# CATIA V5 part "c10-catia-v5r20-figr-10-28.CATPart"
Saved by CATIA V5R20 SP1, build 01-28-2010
Part number: Part1
Bounding box of the stored display mesh (mm): x -60 to 70, y 0 to 100.393, z 0 to 0
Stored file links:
  D:\v5_r20\psrt_files_downloaded\c10\c10-catia-v5r20-figr-10-28.CATPart
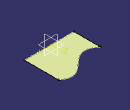
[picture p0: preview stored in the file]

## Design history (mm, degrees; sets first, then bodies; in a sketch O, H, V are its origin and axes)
Set1
  Sweep1: type Segment, GuideCrv (Sketch1; Sketch2), Length1 0, Length2 0
Body1 (main body)
  Sketch1 on xy-plane, origin (0, 0, 0), H (1, 0, 0), V (0, 1, 0)
    line L1 (-60, 0) -> (70, 0)
    point P1 (-60, 0)
    coincidence: P1 H
    horizontal: L1 H
  Sketch2 on xy-plane, origin (0, 0, 0), H (1, 0, 0), V (0, 1, 0)
    spline S1 through (-60, 70) (-20, 60) (40, 100) (70, 90)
